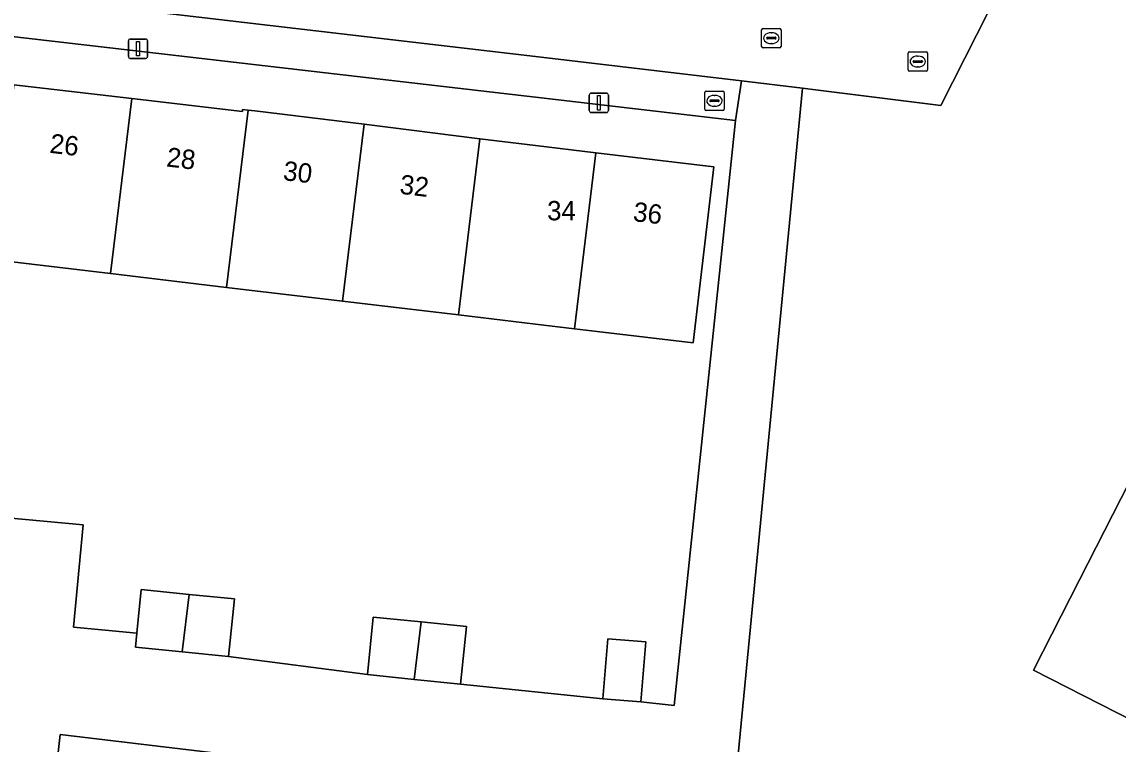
# Model space of a CAD drawing. Extents: x 161241 to 161758, y 384138 to 384885.
# Drawn here: x 161473.4 to 161530.1, y 384452.3 to 384489.7 of the extents above; entities that cross this region are included whole.
import ezdxf

# ---------------------------------------------------------------- set-up
doc = ezdxf.new("R2010")
doc.units = 0
for name, color, linetype in [('IMGEO_Brandkraan', 7, 'Continuous'), ('IMGEO_Erf', 7, 'Continuous'), ('IMGEO_Kolk', 7, 'Continuous'), ('IMGEO_Lichtmast', 7, 'Continuous'), ('IMGEO_Pand', 7, 'Continuous'), ('IMGEO_Pand_nummerreeks', 7, 'Continuous'), ('IMGEO_Rijbaan_lokaal_open', 7, 'Continuous'), ('IMGEO_Rioolput', 7, 'Continuous'), ('IMGEO_Voetpad_open', 7, 'Continuous')]:
    doc.layers.add(name, color=color, linetype=linetype)

msp = doc.modelspace()

# ---------------------------------------------------------------- linework, layer by layer
at = {"layer": 'IMGEO_Brandkraan'}
for p, q in [((161508.761, 384485.174), (161508.761, 384486.026)), ((161508.836, 384486.1), (161509.688, 384486.1)), ((161509.249, 384485.88), (161509.274, 384485.88)), ((161509.762, 384486.026), (161509.762, 384485.174)), ((161509.02, 384485.594), (161509.02, 384485.606)), ((161509.458, 384485.557), (161509.06, 384485.557)), ((161509.063, 384485.643), (161509.461, 384485.643)), ((161509.272, 384485.32), (161509.247, 384485.32)), ((161509.504, 384485.606), (161509.504, 384485.594)), ((161509.688, 384485.1), (161508.836, 384485.1))]:
    msp.add_line(p, q, dxfattribs=at)
for points in [[(161508.761, 384485.174), (161508.761, 384486.026)], [(161508.836, 384486.1), (161509.688, 384486.1)], [(161509.762, 384486.026), (161509.762, 384485.174)], [(161509.688, 384485.1), (161508.836, 384485.1)]]:
    msp.add_lwpolyline(points, dxfattribs=at)
for centre, radius, start, end in [((161508.838, 384486.024), 0.0765, 91.552, 178.448), ((161508.838, 384486.024), 0.0765, 91.552, 178.448), ((161509.686, 384486.024), 0.0765, 1.552, 88.448), ((161509.686, 384486.024), 0.0765, 1.552, 88.448), ((161509.06, 384485.603), 0.0403, 85.8775, 175.7526), ((161509.057, 384485.593), 0.0366, 178.938, 274.7102), ((161509.461, 384485.6), 0.043, 264.8664, 352.4533), ((161509.465, 384485.605), 0.0386, 1.7309, 96.639), ((161508.838, 384485.176), 0.0765, 181.552, 268.448), ((161508.838, 384485.176), 0.0765, 181.552, 268.448), ((161509.686, 384485.176), 0.0765, 271.552, 358.448), ((161509.686, 384485.176), 0.0765, 271.552, 358.448)]:
    msp.add_arc(centre, radius, start, end, dxfattribs=at)
for centre, major_axis, ratio, start_param, end_param in [((161509.248, 384485.6), (-0.387, 0.002), 0.722429, 4.712389, 7.853982), ((161509.273, 384485.6), (-0.39, 0.002), 0.717154, 1.570796, 4.712389)]:
    msp.add_ellipse(centre, major_axis=major_axis, ratio=ratio, start_param=start_param, end_param=end_param, dxfattribs=at)
at = {"layer": 'IMGEO_Erf'}
for points in [[(161523.254, 384566.865), (161544.482, 384564.358), (161544.805, 384567.256), (161545.138, 384570.12), (161546.893, 384585.147), (161552.363, 384584.51), (161557.347, 384583.93), (161554.934, 384563.149), (161549.997, 384563.724), (161547.01, 384536.791), (161539.084, 384521.135), (161528.385, 384500), (161520.975, 384485.363), (161514.621, 384486.15), (161513.81, 384486.25), (161510.292, 384449.829)], [(161533.54, 384452.19), (161525.753, 384456.145), (161528.137, 384460.824), (161533.323, 384471), (161537.947, 384480.074), (161543.125, 384490.234), (161545.574, 384495.041)], [(161470.63, 384464.219), (161476.603, 384463.66), (161476.109, 384458.378), (161479.381, 384458.06), (161479.611, 384460.322), (161482.096, 384460.069), (161484.432, 384459.832), (161484.129, 384456.853), (161491.308, 384455.92), (161491.611, 384458.899), (161494.096, 384458.646), (161496.432, 384458.409), (161496.129, 384455.43), (161503.486, 384454.666), (161503.739, 384457.771), (161505.712, 384457.61), (161505.459, 384454.505), (161507.183, 384454.321), (161510.344, 384484.589), (161500, 384485.79), (161454.323, 384491.094)], [(161473.027, 384486.43), (161479.124, 384485.712), (161484.842, 384485.039), (161484.857, 384485.151), (161485.137, 384485.12), (161485.493, 384485.081), (161491.134, 384484.383), (161497.131, 384483.641), (161500, 384483.286), (161503.128, 384482.915), (161509.234, 384482.192), (161508.155, 384473.086), (161503.19, 384473.675), (161502.023, 384473.813), (161500, 384474.053), (161496.024, 384474.524), (161490.024, 384475.236), (161484.024, 384475.947), (161478.025, 384476.659), (161471.899, 384477.385)], [(161475.421, 384452.824), (161474.948, 384448.66)], [(161495.914, 384450.374), (161475.421, 384452.824)]]:
    msp.add_lwpolyline(points, dxfattribs=at)
at = {"layer": 'IMGEO_Kolk'}
for p, q in [((161511.701, 384488.415), (161511.701, 384489.267)), ((161511.776, 384489.341), (161512.628, 384489.341)), ((161512.702, 384489.267), (161512.702, 384488.415)), ((161511.96, 384488.835), (161511.96, 384488.847)), ((161512.398, 384488.798), (161512, 384488.798)), ((161512.003, 384488.884), (161512.401, 384488.884)), ((161512.189, 384489.121), (161512.214, 384489.121)), ((161512.444, 384488.847), (161512.444, 384488.835)), ((161512.628, 384488.341), (161511.776, 384488.341)), ((161512.212, 384488.561), (161512.187, 384488.561))]:
    msp.add_line(p, q, dxfattribs=at)
for points in [[(161511.701, 384488.415), (161511.701, 384489.267)], [(161511.776, 384489.341), (161512.628, 384489.341)], [(161512.702, 384489.267), (161512.702, 384488.415)], [(161512.628, 384488.341), (161511.776, 384488.341)]]:
    msp.add_lwpolyline(points, dxfattribs=at)
for centre, radius, start, end in [((161511.778, 384489.265), 0.0765, 91.552, 178.448), ((161511.778, 384489.265), 0.0765, 91.552, 178.448), ((161512.626, 384489.265), 0.0765, 1.552, 88.448), ((161512.626, 384489.265), 0.0765, 1.552, 88.448), ((161512, 384488.844), 0.0403, 85.8775, 175.7526), ((161511.997, 384488.834), 0.0366, 178.938, 274.7102), ((161512.401, 384488.841), 0.043, 264.8664, 352.4533), ((161512.405, 384488.846), 0.0386, 1.7309, 96.639), ((161511.778, 384488.417), 0.0765, 181.552, 268.448), ((161511.778, 384488.417), 0.0765, 181.552, 268.448), ((161512.626, 384488.417), 0.0765, 271.552, 358.448), ((161512.626, 384488.417), 0.0765, 271.552, 358.448)]:
    msp.add_arc(centre, radius, start, end, dxfattribs=at)
for centre, major_axis, ratio, start_param, end_param in [((161512.188, 384488.841), (-0.387, 0.002), 0.722429, 4.712389, 7.853982), ((161512.213, 384488.841), (-0.39, 0.002), 0.717154, 1.570796, 4.712389)]:
    msp.add_ellipse(centre, major_axis=major_axis, ratio=ratio, start_param=start_param, end_param=end_param, dxfattribs=at)
at = {"layer": 'IMGEO_Lichtmast'}
for p, q in [((161478.946, 384487.896), (161478.946, 384488.696)), ((161478.946, 384488.696), (161478.946, 384487.896)), ((161479.046, 384488.796), (161479.836, 384488.796)), ((161479.836, 384488.796), (161479.046, 384488.796)), ((161479.936, 384488.696), (161479.936, 384487.896)), ((161479.936, 384487.896), (161479.936, 384488.696)), ((161479.836, 384487.796), (161479.046, 384487.796)), ((161479.046, 384487.796), (161479.836, 384487.796)), ((161502.784, 384485.095), (161502.784, 384485.895)), ((161502.784, 384485.895), (161502.784, 384485.095)), ((161502.884, 384485.995), (161503.674, 384485.995)), ((161503.674, 384485.995), (161502.884, 384485.995)), ((161503.774, 384485.895), (161503.774, 384485.095)), ((161503.774, 384485.095), (161503.774, 384485.895)), ((161503.674, 384484.995), (161502.884, 384484.995)), ((161502.884, 384484.995), (161503.674, 384484.995))]:
    msp.add_line(p, q, dxfattribs=at)
for points in [[(161479.366, 384488.671), (161479.516, 384488.671), (161479.516, 384487.921), (161479.366, 384487.921), (161479.366, 384488.671)], [(161503.204, 384485.87), (161503.354, 384485.87), (161503.354, 384485.12), (161503.204, 384485.12), (161503.204, 384485.87)]]:
    msp.add_lwpolyline(points, dxfattribs=at)
for centre, start, end in [((161479.046, 384488.696), 90, 180), ((161479.046, 384488.696), 90, 180), ((161479.836, 384488.696), 0, 90), ((161479.836, 384488.696), 360, 90), ((161479.046, 384487.896), 180, 270), ((161479.046, 384487.896), 180, 270), ((161479.836, 384487.896), 270, 0), ((161479.836, 384487.896), 270, 0), ((161502.884, 384485.895), 90, 180), ((161502.884, 384485.895), 90, 180), ((161503.674, 384485.895), 0, 90), ((161503.674, 384485.895), 360, 90), ((161502.884, 384485.095), 180, 270), ((161502.884, 384485.095), 180, 270), ((161503.674, 384485.095), 270, 0), ((161503.674, 384485.095), 270, 0)]:
    msp.add_arc(centre, 0.1, start, end, dxfattribs=at)
at = {"layer": 'IMGEO_Pand'}
for points in [[(161479.124, 384485.712), (161473.027, 384486.43), (161472.817, 384484.707), (161471.99, 384478.301), (161471.899, 384477.385), (161478.025, 384476.659)], [(161478.025, 384476.659), (161484.024, 384475.947), (161485.137, 384485.12), (161484.857, 384485.151), (161484.842, 384485.039), (161479.124, 384485.712)], [(161484.024, 384475.947), (161490.024, 384475.236), (161491.134, 384484.383), (161485.493, 384485.081), (161485.137, 384485.12)], [(161497.131, 384483.641), (161491.134, 384484.383), (161490.024, 384475.236), (161496.024, 384474.524)], [(161496.024, 384474.524), (161500, 384474.053), (161502.023, 384473.813), (161503.128, 384482.915), (161500, 384483.286), (161497.131, 384483.641)], [(161502.023, 384473.813), (161503.19, 384473.675), (161508.155, 384473.086), (161509.234, 384482.192), (161503.128, 384482.915)], [(161482.096, 384460.069), (161479.611, 384460.322), (161479.381, 384458.06), (161479.308, 384457.343), (161481.735, 384457.096)], [(161484.129, 384456.853), (161484.432, 384459.832), (161482.096, 384460.069), (161481.735, 384457.096)], [(161491.611, 384458.899), (161491.308, 384455.92), (161493.735, 384455.673), (161494.096, 384458.646)], [(161496.129, 384455.43), (161496.432, 384458.409), (161494.096, 384458.646), (161493.735, 384455.673)], [(161503.739, 384457.771), (161503.486, 384454.666), (161505.459, 384454.505), (161505.712, 384457.61)]]:
    msp.add_lwpolyline(points, close=True, dxfattribs=at)
msp.add_lwpolyline([(161533.323, 384471), (161528.137, 384460.824), (161525.753, 384456.145), (161533.54, 384452.19)], dxfattribs=at)
at = {"layer": 'IMGEO_Rijbaan_lokaal_open'}
for points in [[(161513.174, 384491.028), (161506.677, 384491.817), (161500, 384492.603), (161498.849, 384492.738), (161473.721, 384495.685), (161456.261, 384497.821), (161442.259, 384499.359), (161436.769, 384500), (161430.603, 384500.72), (161430.519, 384500), (161430.062, 384496.065), (161448.776, 384493.891), (161500, 384487.889), (161510.654, 384486.641), (161513.81, 384486.25), (161514.621, 384486.15), (161520.975, 384485.363), (161528.385, 384500), (161539.084, 384521.135)], [(161510.292, 384449.829), (161513.81, 384486.25), (161510.654, 384486.641), (161510.344, 384484.589), (161507.183, 384454.321), (161505.459, 384454.505), (161503.486, 384454.666), (161496.129, 384455.43), (161493.735, 384455.673), (161491.308, 384455.92), (161484.129, 384456.853), (161481.735, 384457.096), (161479.308, 384457.343), (161479.381, 384458.06), (161476.109, 384458.378), (161476.603, 384463.66), (161470.63, 384464.219), (161470.488, 384462.99), (161470.258, 384463.016), (161469.377, 384455.762), (161469.656, 384455.728), (161469.382, 384453.472), (161469.103, 384453.506), (161468.649, 384449.709)], [(161474.948, 384448.66), (161475.421, 384452.824), (161495.914, 384450.374)]]:
    msp.add_lwpolyline(points, dxfattribs=at)
at = {"layer": 'IMGEO_Rioolput'}
for p, q in [((161519.352, 384488.13), (161520.204, 384488.13)), ((161519.277, 384487.204), (161519.277, 384488.056)), ((161519.536, 384487.624), (161519.536, 384487.636)), ((161519.974, 384487.587), (161519.576, 384487.587)), ((161519.579, 384487.673), (161519.977, 384487.673)), ((161519.765, 384487.91), (161519.79, 384487.91)), ((161520.02, 384487.636), (161520.02, 384487.624)), ((161520.278, 384488.056), (161520.278, 384487.204)), ((161520.204, 384487.13), (161519.352, 384487.13)), ((161519.788, 384487.35), (161519.763, 384487.35))]:
    msp.add_line(p, q, dxfattribs=at)
for points in [[(161519.352, 384488.13), (161520.204, 384488.13)], [(161519.277, 384487.204), (161519.277, 384488.056)], [(161520.278, 384488.056), (161520.278, 384487.204)], [(161520.204, 384487.13), (161519.352, 384487.13)]]:
    msp.add_lwpolyline(points, dxfattribs=at)
for centre, radius, start, end in [((161519.354, 384488.054), 0.0765, 91.552, 178.448), ((161519.354, 384488.054), 0.0765, 91.552, 178.448), ((161520.202, 384488.054), 0.0765, 1.552, 88.448), ((161520.202, 384488.054), 0.0765, 1.552, 88.448), ((161519.576, 384487.633), 0.0403, 85.8775, 175.7526), ((161519.573, 384487.623), 0.0366, 178.938, 274.7102), ((161519.977, 384487.63), 0.043, 264.8664, 352.4533), ((161519.981, 384487.635), 0.0386, 1.7309, 96.639), ((161519.354, 384487.206), 0.0765, 181.552, 268.448), ((161519.354, 384487.206), 0.0765, 181.552, 268.448), ((161520.202, 384487.206), 0.0765, 271.552, 358.448), ((161520.202, 384487.206), 0.0765, 271.552, 358.448)]:
    msp.add_arc(centre, radius, start, end, dxfattribs=at)
for centre, major_axis, ratio, start_param, end_param in [((161519.764, 384487.63), (-0.387, 0.002), 0.722429, 4.712389, 7.853982), ((161519.789, 384487.63), (-0.39, 0.002), 0.717154, 1.570796, 4.712389)]:
    msp.add_ellipse(centre, major_axis=major_axis, ratio=ratio, start_param=start_param, end_param=end_param, dxfattribs=at)
at = {"layer": 'IMGEO_Voetpad_open'}
msp.add_lwpolyline([(161430.062, 384496.065), (161427.321, 384496.383), (161396.178, 384500), (161357.097, 384504.581), (161354.376, 384504.9), (161340.82, 384506.489), (161340.647, 384506.515), (161340.403, 384504.377), (161341.704, 384504.225), (161377.935, 384500), (161395.453, 384497.957), (161401.111, 384497.3), (161421.466, 384494.929), (161433, 384493.585), (161437.975, 384493.006), (161442.515, 384492.47), (161448.511, 384491.779), (161454.323, 384491.094), (161500, 384485.79), (161510.344, 384484.589), (161510.654, 384486.641), (161500, 384487.889), (161448.776, 384493.891)], close=True, dxfattribs=at)

# ---------------------------------------------------------------- texts
at = {"layer": 'IMGEO_Pand_nummerreeks'}
for s, p in [('26', (161474.842, 384482.914)), ('28', (161480.88, 384482.208)), ('30', (161486.914, 384481.502)), ('32', (161492.943, 384480.796)), ('36', (161505.015, 384479.383))]:
    msp.add_text(s, height=1, rotation=353.324, dxfattribs=at).set_placement(p)
msp.add_text('34', height=1, dxfattribs=at).set_placement((161500.604, 384479.418))

doc.saveas('drawing.dxf')
